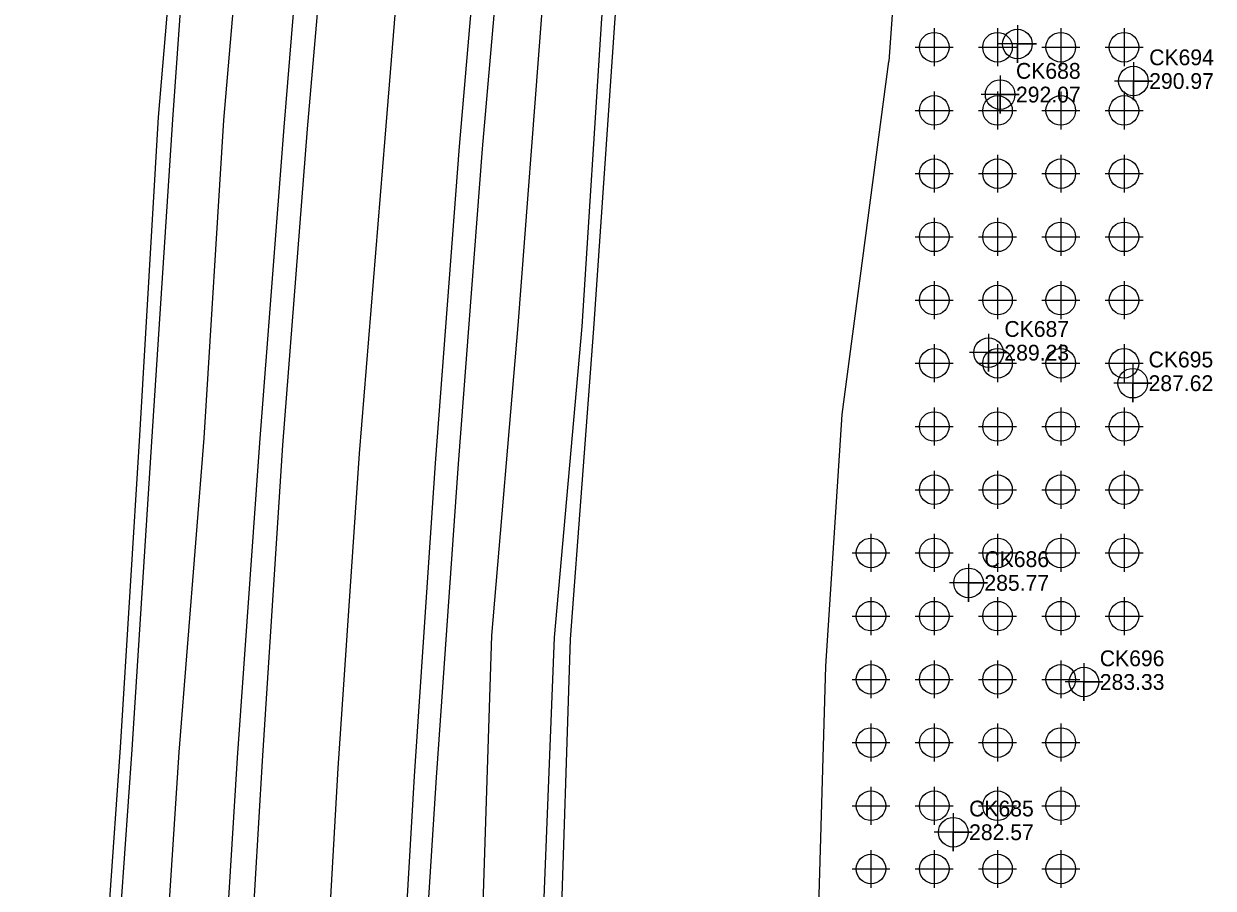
# Model space of a CAD drawing. Extents: x 1941547 to 1942851, y 663002 to 668358.
# Drawn here: x 1941926.1 to 1942114.1, y 667807 to 667943.7 of the extents above; entities that cross this region are included whole.
import ezdxf

# ---------------------------------------------------------------- set-up
doc = ezdxf.new("R2010")
doc.units = 0
for name, color, linetype in [('CTL GPS Vertical Cogo Elevation', 7, 'Continuous'), ('CTL NGS Vertical CELL', 7, 'Continuous'), ('Exist DTM Drainline Cogo Elevation', 7, 'Continuous'), ('Exist DTM QL2 LIDAR Elevation Point', 7, 'Continuous'), ('Exist Property Iron Pin Cogo Number', 7, 'Continuous'), ('Exist Roads EOP Cogo Point CELL', 7, 'Continuous'), ('Exist Roads EOT', 7, 'Continuous'), ('Exist Utilities Telephone UG Cable SUE LOS C Cogo Elevation', 7, 'Continuous'), ('Exist Utilities Telephone UG FO SUE LOS C Cogo Elevation', 7, 'Continuous')]:
    doc.layers.add(name, color=color, linetype=linetype)

msp = doc.modelspace()

# ---------------------------------------------------------------- linework, layer by layer
at = {"layer": 'CTL NGS Vertical CELL'}
for points in [[(1942024.37, 668012.57), (1942022.28, 667994.37), (1942017.39, 667944.52), (1942014.27, 667895.82), (1942009.92, 667846.63), (1942007.93, 667796.15), (1942005.97, 667746.35), (1942004.4, 667697.91), (1942000.78, 667648.26), (1941999.86, 667599.46), (1941998.39, 667548.71), (1942000.68, 667500.48)], [(1942026.8, 668012.52), (1942024.33, 667994.23), (1942019.53, 667944.62), (1942016.16, 667895.49), (1942012.43, 667846.36), (1942010.79, 667795.94), (1942008.34, 667746.43), (1942008.34, 667697.72), (1942004.96, 667648.49), (1942005.04, 667599.29), (1942003.6, 667548.44), (1942003.59, 667500.58)], [(1941930.54, 667422.84), (1941928.68, 667463.46), (1941928.78, 667514.02), (1941930.06, 667568.07), (1941931.99, 667622.09), (1941933.48, 667674.51), (1941937.26, 667726.95), (1941939.71, 667779.55), (1941943.19, 667828.89), (1941946.38, 667878.43), (1941949.61, 667928.57), (1941952.29, 667965.88), (1941953.97, 667997.88)], [(1941928.41, 667422.42), (1941926.07, 667463.45), (1941926.54, 667514.2), (1941927.95, 667567.47), (1941929.84, 667622.24), (1941931.61, 667674.49), (1941934.69, 667727.1), (1941937.88, 667779.66), (1941941.36, 667829.21), (1941944.43, 667878.58), (1941947.39, 667928.96), (1941950.55, 667966.21)]]:
    msp.add_lwpolyline(points, dxfattribs=at)
at = {"layer": 'Exist DTM Drainline Cogo Elevation'}
for points in [[(1942083.14, 667943.51), (1942083.14, 667937.51), (1942083.14, 667940.51), (1942086.14, 667940.51), (1942080.14, 667940.51)], [(1942101.48, 667937.65), (1942101.48, 667931.65), (1942101.48, 667934.65), (1942104.48, 667934.65), (1942098.48, 667934.65)], [(1942101.48, 667937.65), (1942101.48, 667931.65), (1942101.48, 667934.65), (1942104.48, 667934.65), (1942098.48, 667934.65)], [(1942080.42, 667935.51), (1942080.42, 667929.51), (1942080.42, 667932.51), (1942083.42, 667932.51), (1942077.42, 667932.51)], [(1942080.42, 667935.51), (1942080.42, 667929.51), (1942080.42, 667932.51), (1942083.42, 667932.51), (1942077.42, 667932.51)], [(1942078.59, 667894.68), (1942078.59, 667888.68), (1942078.59, 667891.68), (1942081.59, 667891.68), (1942075.59, 667891.68)], [(1942078.59, 667894.68), (1942078.59, 667888.68), (1942078.59, 667891.68), (1942081.59, 667891.68), (1942075.59, 667891.68)], [(1942101.38, 667889.85), (1942101.38, 667883.85), (1942101.38, 667886.85), (1942104.38, 667886.85), (1942098.38, 667886.85)], [(1942101.38, 667889.85), (1942101.38, 667883.85), (1942101.38, 667886.85), (1942104.38, 667886.85), (1942098.38, 667886.85)], [(1942075.43, 667858.26), (1942075.43, 667852.26), (1942075.43, 667855.26), (1942078.43, 667855.26), (1942072.43, 667855.26)], [(1942075.43, 667858.26), (1942075.43, 667852.26), (1942075.43, 667855.26), (1942078.43, 667855.26), (1942072.43, 667855.26)], [(1942093.67, 667842.58), (1942093.67, 667836.58), (1942093.67, 667839.58), (1942096.67, 667839.58), (1942090.67, 667839.58)], [(1942093.67, 667842.58), (1942093.67, 667836.58), (1942093.67, 667839.58), (1942096.67, 667839.58), (1942090.67, 667839.58)], [(1942073.01, 667818.81), (1942073.01, 667812.81), (1942073.01, 667815.81), (1942076.01, 667815.81), (1942070.01, 667815.81)], [(1942073.01, 667818.81), (1942073.01, 667812.81), (1942073.01, 667815.81), (1942076.01, 667815.81), (1942070.01, 667815.81)]]:
    msp.add_lwpolyline(points, dxfattribs=at)
for centre in [(1942083.14, 667940.51), (1942101.48, 667934.65), (1942101.48, 667934.65), (1942080.42, 667932.51), (1942080.42, 667932.51), (1942078.59, 667891.68), (1942078.59, 667891.68), (1942101.38, 667886.85), (1942101.38, 667886.85), (1942075.43, 667855.26), (1942075.43, 667855.26), (1942093.67, 667839.58), (1942093.67, 667839.58), (1942073.01, 667815.81), (1942073.01, 667815.81)]:
    msp.add_circle(centre, 2.34, dxfattribs=at)
at = {"layer": 'Exist DTM QL2 LIDAR Elevation Point'}
for points in [[(1942070, 667943), (1942070, 667940)], [(1942080, 667943), (1942080, 667940)], [(1942090, 667943), (1942090, 667940)], [(1942100, 667943), (1942100, 667940)], [(1942067, 667940), (1942070, 667940)], [(1942070, 667940), (1942073, 667940)], [(1942070, 667940), (1942070, 667937)], [(1942077, 667940), (1942080, 667940)], [(1942080, 667940), (1942083, 667940)], [(1942080, 667940), (1942080, 667937)], [(1942087, 667940), (1942090, 667940)], [(1942090, 667940), (1942093, 667940)], [(1942090, 667940), (1942090, 667937)], [(1942097, 667940), (1942100, 667940)], [(1942100, 667940), (1942103, 667940)], [(1942100, 667940), (1942100, 667937)], [(1942070, 667933), (1942070, 667930)], [(1942080, 667933), (1942080, 667930)], [(1942090, 667933), (1942090, 667930)], [(1942100, 667933), (1942100, 667930)], [(1942067, 667930), (1942070, 667930)], [(1942070, 667930), (1942073, 667930)], [(1942070, 667930), (1942070, 667927)], [(1942077, 667930), (1942080, 667930)], [(1942080, 667930), (1942083, 667930)], [(1942080, 667930), (1942080, 667927)], [(1942087, 667930), (1942090, 667930)], [(1942090, 667930), (1942093, 667930)], [(1942090, 667930), (1942090, 667927)], [(1942097, 667930), (1942100, 667930)], [(1942100, 667930), (1942103, 667930)], [(1942100, 667930), (1942100, 667927)], [(1942070, 667923), (1942070, 667920)], [(1942080, 667923), (1942080, 667920)], [(1942090, 667923), (1942090, 667920)], [(1942100, 667923), (1942100, 667920)], [(1942067, 667920), (1942070, 667920)], [(1942070, 667920), (1942073, 667920)], [(1942070, 667920), (1942070, 667917)], [(1942077, 667920), (1942080, 667920)], [(1942080, 667920), (1942083, 667920)], [(1942080, 667920), (1942080, 667917)], [(1942087, 667920), (1942090, 667920)], [(1942090, 667920), (1942093, 667920)], [(1942090, 667920), (1942090, 667917)], [(1942097, 667920), (1942100, 667920)], [(1942100, 667920), (1942103, 667920)], [(1942100, 667920), (1942100, 667917)], [(1942070, 667913), (1942070, 667910)], [(1942080, 667913), (1942080, 667910)], [(1942090, 667913), (1942090, 667910)], [(1942100, 667913), (1942100, 667910)], [(1942067, 667910), (1942070, 667910)], [(1942070, 667910), (1942073, 667910)], [(1942070, 667910), (1942070, 667907)], [(1942077, 667910), (1942080, 667910)], [(1942080, 667910), (1942083, 667910)], [(1942080, 667910), (1942080, 667907)], [(1942087, 667910), (1942090, 667910)], [(1942090, 667910), (1942093, 667910)], [(1942090, 667910), (1942090, 667907)], [(1942097, 667910), (1942100, 667910)], [(1942100, 667910), (1942103, 667910)], [(1942100, 667910), (1942100, 667907)], [(1942070, 667903), (1942070, 667900)], [(1942080, 667903), (1942080, 667900)], [(1942090, 667903), (1942090, 667900)], [(1942100, 667903), (1942100, 667900)], [(1942067, 667900), (1942070, 667900)], [(1942070, 667900), (1942073, 667900)], [(1942070, 667900), (1942070, 667897)], [(1942077, 667900), (1942080, 667900)], [(1942080, 667900), (1942083, 667900)], [(1942080, 667900), (1942080, 667897)], [(1942087, 667900), (1942090, 667900)], [(1942090, 667900), (1942093, 667900)], [(1942090, 667900), (1942090, 667897)], [(1942097, 667900), (1942100, 667900)], [(1942100, 667900), (1942103, 667900)], [(1942100, 667900), (1942100, 667897)], [(1942070, 667893), (1942070, 667890)], [(1942080, 667893), (1942080, 667890)], [(1942090, 667893), (1942090, 667890)], [(1942100, 667893), (1942100, 667890)], [(1942067, 667890), (1942070, 667890)], [(1942070, 667890), (1942073, 667890)], [(1942070, 667890), (1942070, 667887)], [(1942077, 667890), (1942080, 667890)], [(1942080, 667890), (1942083, 667890)], [(1942080, 667890), (1942080, 667887)], [(1942087, 667890), (1942090, 667890)], [(1942090, 667890), (1942093, 667890)], [(1942090, 667890), (1942090, 667887)], [(1942097, 667890), (1942100, 667890)], [(1942100, 667890), (1942103, 667890)], [(1942100, 667890), (1942100, 667887)], [(1942070, 667883), (1942070, 667880)], [(1942080, 667883), (1942080, 667880)], [(1942090, 667883), (1942090, 667880)], [(1942100, 667883), (1942100, 667880)], [(1942067, 667880), (1942070, 667880)], [(1942070, 667880), (1942073, 667880)], [(1942070, 667880), (1942070, 667877)], [(1942077, 667880), (1942080, 667880)], [(1942080, 667880), (1942083, 667880)], [(1942080, 667880), (1942080, 667877)], [(1942087, 667880), (1942090, 667880)], [(1942090, 667880), (1942093, 667880)], [(1942090, 667880), (1942090, 667877)], [(1942097, 667880), (1942100, 667880)], [(1942100, 667880), (1942103, 667880)], [(1942100, 667880), (1942100, 667877)], [(1942070, 667873), (1942070, 667870)], [(1942080, 667873), (1942080, 667870)], [(1942090, 667873), (1942090, 667870)], [(1942100, 667873), (1942100, 667870)], [(1942067, 667870), (1942070, 667870)], [(1942070, 667870), (1942073, 667870)], [(1942070, 667870), (1942070, 667867)], [(1942077, 667870), (1942080, 667870)], [(1942080, 667870), (1942083, 667870)], [(1942080, 667870), (1942080, 667867)], [(1942087, 667870), (1942090, 667870)], [(1942090, 667870), (1942093, 667870)], [(1942090, 667870), (1942090, 667867)], [(1942097, 667870), (1942100, 667870)], [(1942100, 667870), (1942103, 667870)], [(1942100, 667870), (1942100, 667867)], [(1942060, 667863), (1942060, 667860)], [(1942070, 667863), (1942070, 667860)], [(1942080, 667863), (1942080, 667860)], [(1942090, 667863), (1942090, 667860)], [(1942100, 667863), (1942100, 667860)], [(1942057, 667860), (1942060, 667860)], [(1942060, 667860), (1942063, 667860)], [(1942060, 667860), (1942060, 667857)], [(1942067, 667860), (1942070, 667860)], [(1942070, 667860), (1942073, 667860)], [(1942070, 667860), (1942070, 667857)], [(1942077, 667860), (1942080, 667860)], [(1942080, 667860), (1942083, 667860)], [(1942080, 667860), (1942080, 667857)], [(1942087, 667860), (1942090, 667860)], [(1942090, 667860), (1942093, 667860)], [(1942090, 667860), (1942090, 667857)], [(1942097, 667860), (1942100, 667860)], [(1942100, 667860), (1942103, 667860)], [(1942100, 667860), (1942100, 667857)], [(1942060, 667853), (1942060, 667850)], [(1942070, 667853), (1942070, 667850)], [(1942080, 667853), (1942080, 667850)], [(1942090, 667853), (1942090, 667850)], [(1942100, 667853), (1942100, 667850)], [(1942057, 667850), (1942060, 667850)], [(1942060, 667850), (1942063, 667850)], [(1942060, 667850), (1942060, 667847)], [(1942067, 667850), (1942070, 667850)], [(1942070, 667850), (1942073, 667850)], [(1942070, 667850), (1942070, 667847)], [(1942077, 667850), (1942080, 667850)], [(1942080, 667850), (1942083, 667850)], [(1942080, 667850), (1942080, 667847)], [(1942087, 667850), (1942090, 667850)], [(1942090, 667850), (1942093, 667850)], [(1942090, 667850), (1942090, 667847)], [(1942097, 667850), (1942100, 667850)], [(1942100, 667850), (1942103, 667850)], [(1942100, 667850), (1942100, 667847)], [(1942060, 667843), (1942060, 667840)], [(1942070, 667843), (1942070, 667840)], [(1942080, 667843), (1942080, 667840)], [(1942090, 667843), (1942090, 667840)], [(1942057, 667840), (1942060, 667840)], [(1942060, 667840), (1942063, 667840)], [(1942060, 667840), (1942060, 667837)], [(1942067, 667840), (1942070, 667840)], [(1942070, 667840), (1942073, 667840)], [(1942070, 667840), (1942070, 667837)], [(1942077, 667840), (1942080, 667840)], [(1942080, 667840), (1942083, 667840)], [(1942080, 667840), (1942080, 667837)], [(1942087, 667840), (1942090, 667840)], [(1942090, 667840), (1942093, 667840)], [(1942090, 667840), (1942090, 667837)], [(1942060, 667833), (1942060, 667830)], [(1942070, 667833), (1942070, 667830)], [(1942080, 667833), (1942080, 667830)], [(1942090, 667833), (1942090, 667830)], [(1942057, 667830), (1942060, 667830)], [(1942060, 667830), (1942063, 667830)], [(1942060, 667830), (1942060, 667827)], [(1942067, 667830), (1942070, 667830)], [(1942070, 667830), (1942073, 667830)], [(1942070, 667830), (1942070, 667827)], [(1942077, 667830), (1942080, 667830)], [(1942080, 667830), (1942083, 667830)], [(1942080, 667830), (1942080, 667827)], [(1942087, 667830), (1942090, 667830)], [(1942090, 667830), (1942093, 667830)], [(1942090, 667830), (1942090, 667827)], [(1942060, 667823), (1942060, 667820)], [(1942070, 667823), (1942070, 667820)], [(1942080, 667823), (1942080, 667820)], [(1942090, 667823), (1942090, 667820)], [(1942057, 667820), (1942060, 667820)], [(1942060, 667820), (1942063, 667820)], [(1942060, 667820), (1942060, 667817)], [(1942067, 667820), (1942070, 667820)], [(1942070, 667820), (1942073, 667820)], [(1942070, 667820), (1942070, 667817)], [(1942077, 667820), (1942080, 667820)], [(1942080, 667820), (1942083, 667820)], [(1942080, 667820), (1942080, 667817)], [(1942087, 667820), (1942090, 667820)], [(1942090, 667820), (1942093, 667820)], [(1942090, 667820), (1942090, 667817)], [(1942060, 667813), (1942060, 667810)], [(1942070, 667813), (1942070, 667810)], [(1942080, 667813), (1942080, 667810)], [(1942090, 667813), (1942090, 667810)], [(1942057, 667810), (1942060, 667810)], [(1942060, 667810), (1942063, 667810)], [(1942060, 667810), (1942060, 667807)], [(1942067, 667810), (1942070, 667810)], [(1942070, 667810), (1942073, 667810)], [(1942070, 667810), (1942070, 667807)], [(1942077, 667810), (1942080, 667810)], [(1942080, 667810), (1942083, 667810)], [(1942080, 667810), (1942080, 667807)], [(1942087, 667810), (1942090, 667810)], [(1942090, 667810), (1942093, 667810)], [(1942090, 667810), (1942090, 667807)]]:
    msp.add_lwpolyline(points, dxfattribs=at)
for centre in [(1942070, 667940), (1942080, 667940), (1942090, 667940), (1942100, 667940), (1942070, 667930), (1942080, 667930), (1942090, 667930), (1942100, 667930), (1942070, 667920), (1942080, 667920), (1942090, 667920), (1942100, 667920), (1942070, 667910), (1942080, 667910), (1942090, 667910), (1942100, 667910), (1942070, 667900), (1942080, 667900), (1942090, 667900), (1942100, 667900), (1942070, 667890), (1942080, 667890), (1942090, 667890), (1942100, 667890), (1942070, 667880), (1942080, 667880), (1942090, 667880), (1942100, 667880), (1942070, 667870), (1942080, 667870), (1942090, 667870), (1942100, 667870), (1942060, 667860), (1942070, 667860), (1942080, 667860), (1942090, 667860), (1942100, 667860), (1942060, 667850), (1942070, 667850), (1942080, 667850), (1942090, 667850), (1942100, 667850), (1942060, 667840), (1942070, 667840), (1942080, 667840), (1942090, 667840), (1942060, 667830), (1942070, 667830), (1942080, 667830), (1942090, 667830), (1942060, 667820), (1942070, 667820), (1942080, 667820), (1942090, 667820), (1942060, 667810), (1942070, 667810), (1942080, 667810), (1942090, 667810)]:
    msp.add_circle(centre, 2.34, dxfattribs=at)
at = {"layer": 'Exist Property Iron Pin Cogo Number'}
msp.add_lwpolyline([(1941986.94, 667972.46), (1941983.14, 667925.62), (1941979.11, 667875.72), (1941975.71, 667825.96), (1941972.91, 667776.76), (1941970.2, 667724.07), (1941967.78, 667672.14), (1941966.03, 667619.74), (1941964.82, 667566.56), (1941964.04, 667513.11), (1941963.9, 667463.6), (1941963.98, 667414.3)], dxfattribs=at)
at = {"layer": 'Exist Roads EOT'}
for points in [[(1941951.96, 667414.49), (1941951.82, 667463.66), (1941951.89, 667513.47), (1941952.66, 667567.03), (1941954.12, 667620.18), (1941955.74, 667673.09), (1941958.11, 667725.12), (1941960.9, 667778.05), (1941963.81, 667827.1), (1941967.02, 667877.05), (1941970.92, 667927.07), (1941974.94, 667973.32)], [(1941998.95, 667971.48), (1941994.9, 667924.27), (1941991.1, 667874.21), (1941987.79, 667824.66), (1941984.92, 667775.88), (1941982.17, 667722.97), (1941979.79, 667671.47), (1941977.97, 667618.81), (1941976.79, 667566.11), (1941976.12, 667512.58), (1941975.9, 667463.33), (1941975.97, 667414.74)]]:
    msp.add_lwpolyline(points, dxfattribs=at)
at = {"layer": 'Exist Utilities Telephone UG Cable SUE LOS C Cogo Elevation'}
for points in [[(1941947.52, 667414.49), (1941948.18, 667463.95), (1941948.33, 667513.56), (1941948.74, 667567.19), (1941950.01, 667620.48), (1941951.44, 667673.18), (1941953.79, 667725.44), (1941956.78, 667778.06), (1941959.88, 667827.56), (1941963.38, 667877.42), (1941967.24, 667927.35), (1941971.03, 667973.65)], [(1942002.64, 667971.13), (1941998.56, 667923.93), (1941994.72, 667874.07), (1941991.26, 667824.47), (1941988.15, 667775.69), (1941985.27, 667722.8), (1941983.08, 667671.41), (1941981.48, 667618.83), (1941980.44, 667566), (1941979.8, 667512.63), (1941979.4, 667463.31), (1941979.4, 667414.56)]]:
    msp.add_lwpolyline(points, dxfattribs=at)
at = {"layer": 'Exist Utilities Telephone UG FO SUE LOS C Cogo Elevation'}
msp.add_line((1942055.45, 667881.88), (1942062.82, 667937.72), dxfattribs=at)
for points in [[(1942015.16, 668036.81), (1942013.71, 667994.65), (1942007.92, 667945.04), (1942004.16, 667896), (1942000.03, 667846.93), (1941998.38, 667796.26), (1941995.44, 667746.75), (1941992.37, 667698.24), (1941991.14, 667648.1), (1941991.07, 667599.08), (1941991.51, 667548.12), (1941993.3, 667500.89), (1941997.12, 667495.7), (1942004.5, 667494.55), (1942017.16, 667495.67), (1942033.91, 667493.9), (1942061.43, 667495.96)], [(1942073.81, 668032.13), (1942065.44, 667974.81), (1942062.82, 667937.72)], [(1941938.12, 667401.41), (1941938.73, 667423.66), (1941941.78, 667464.33), (1941941.12, 667514.11), (1941938.71, 667567.68), (1941940.02, 667621.54), (1941943.32, 667673.83), (1941944.97, 667726.11), (1941947.44, 667778.97), (1941950.62, 667828.46), (1941954.58, 667878.17), (1941957.72, 667928.48), (1941960.86, 667965.38), (1941963.56, 667974.26)], [(1942061.44, 667498.89), (1942036.78, 667507.17), (1942035.13, 667516.78), (1942045.76, 667564.8), (1942041.25, 667609.68), (1942043.79, 667655.13), (1942048.71, 667688.84), (1942047.6, 667738.81), (1942051.48, 667794.98), (1942052.88, 667842.09), (1942055.45, 667881.88)]]:
    msp.add_lwpolyline(points, dxfattribs=at)

# ---------------------------------------------------------------- texts
at = {"layer": 'CTL GPS Vertical Cogo Elevation'}
for s, p in [('CK694', (1942103.98, 667937.15)), ('CK688', (1942082.92, 667935.01)), ('CK687', (1942081.09, 667894.18)), ('CK695', (1942103.88, 667889.35)), ('CK686', (1942077.93, 667857.76)), ('CK696', (1942096.17, 667842.08)), ('CK685', (1942075.51, 667818.31))]:
    msp.add_text(s, height=2.5, dxfattribs=at).set_placement(p)
at = {"layer": 'Exist Roads EOP Cogo Point CELL'}
for s, p in [('290.97', (1942103.98, 667933.4)), ('292.07', (1942082.92, 667931.26)), ('289.23', (1942081.09, 667890.43)), ('287.62', (1942103.88, 667885.6)), ('285.77', (1942077.93, 667854.01)), ('283.33', (1942096.17, 667838.33)), ('282.57', (1942075.51, 667814.56))]:
    msp.add_text(s, height=2.5, dxfattribs=at).set_placement(p)

doc.saveas('drawing.dxf')
